(* Logix 5000 project; controller CIP_Sync_Essentials_Sample_Project_2_1 vendor 1 type 14 code 156 rev 34.11; software revision 34.01; part 2 of 4 *)
(* CIP_Axis_Home, continued *)

ROUTINE Logic   (* ladder *)
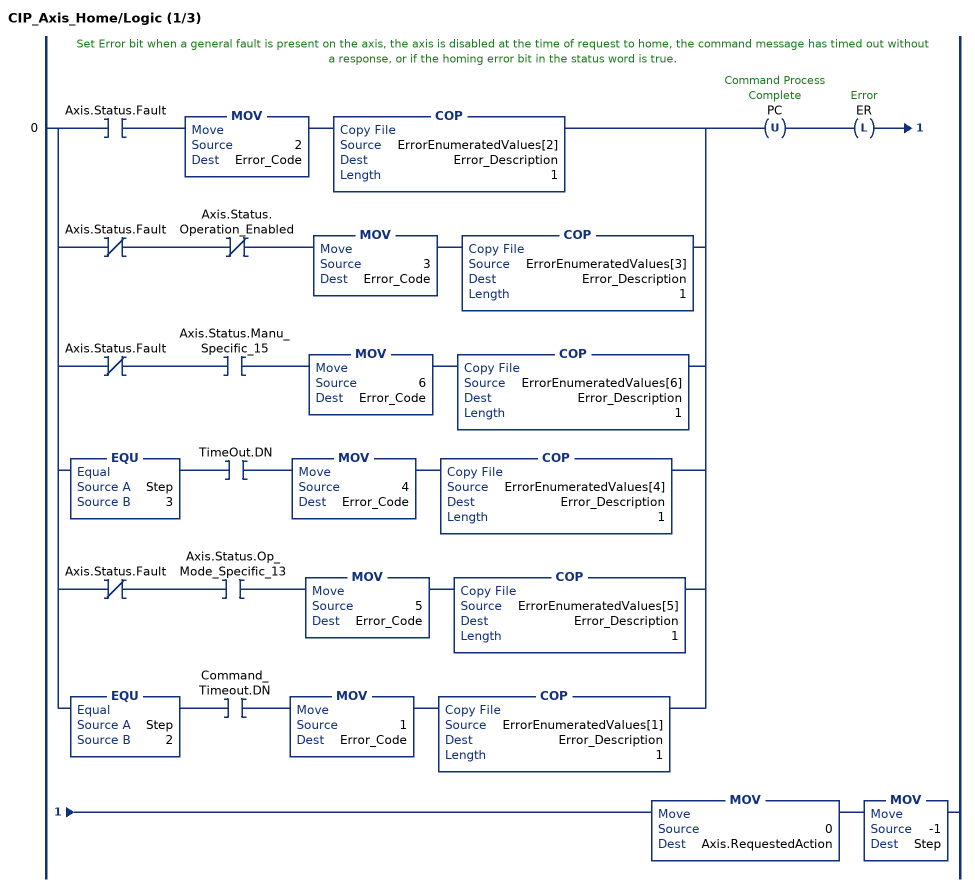
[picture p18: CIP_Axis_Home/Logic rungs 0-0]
   // Set Error bit when a general fault is present on the axis, the axis is disabled at the time of request to home, the command message has timed out without a response, or if the homing error bit in the status word is true.
   0: [XIC(Axis.Status.Fault) MOV(2,Error_Code) COP(ErrorEnumeratedValues[2],Error_Description,1) ,XIO(Axis.Status.Fault) XIO(Axis.Status.Operation_Enabled) MOV(3,Error_Code) COP(ErrorEnumeratedValues[3],Error_Description,1) ,XIO(Axis.Status.Fault) XIC(Axis.Status.Manu_Specific_15) MOV(6,Error_Code) COP(ErrorEnumeratedValues[6],Error_Description,1) ,EQU(Step,3) XIC(TimeOut.DN) MOV(4,Error_Code) COP(ErrorEnumeratedValues[4],Error_Description,1) ,XIO(Axis.Status.Fault) XIC(Axis.Status.Op_Mode_Specific_13) MOV(5,Error_Code) COP(ErrorEnumeratedValues[5],Error_Description,1) ,EQU(Step,2) XIC(Command_Timeout.DN) MOV(1,Error_Code) COP(ErrorEnumeratedValues[1],Error_Description,1) ]OTU(PC)OTL(ER)MOV(0,Axis.RequestedAction)MOV(-1,Step);
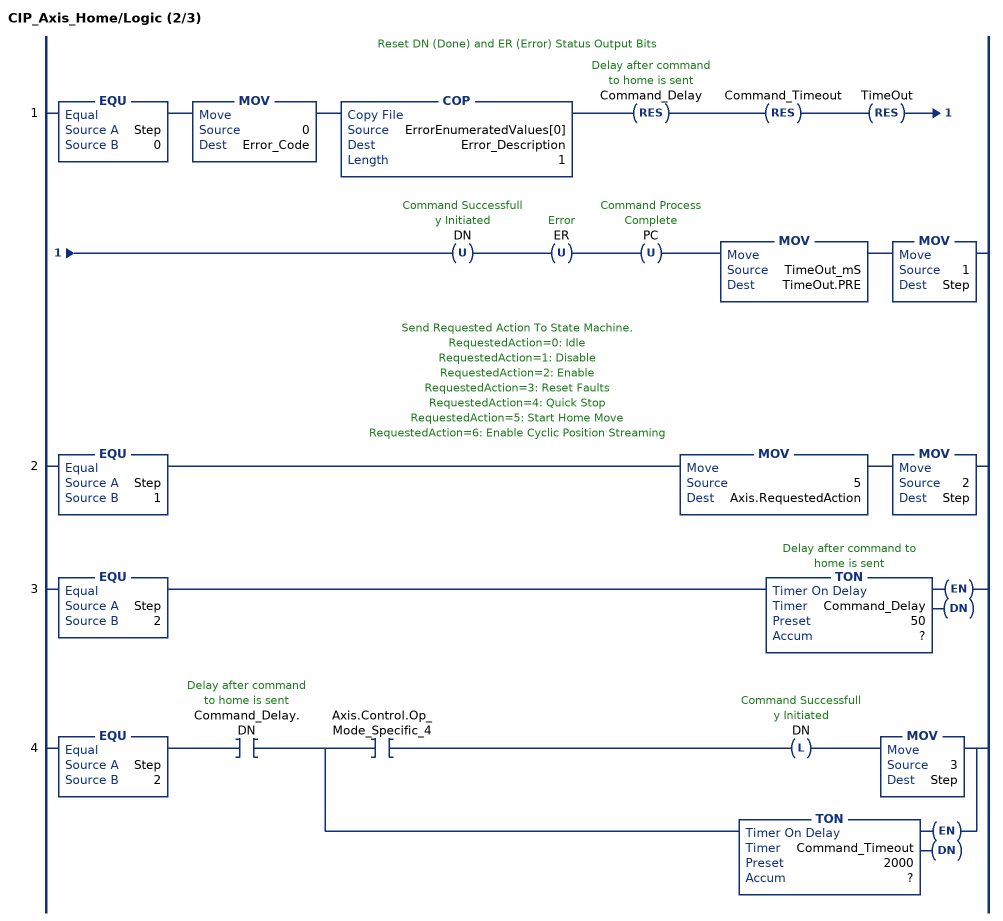
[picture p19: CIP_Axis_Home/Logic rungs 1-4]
   // Reset DN (Done) and ER (Error) Status Output Bits
   1: EQU(Step,0)MOV(0,Error_Code)COP(ErrorEnumeratedValues[0],Error_Description,1)RES(Command_Delay)RES(Command_Timeout)RES(TimeOut)OTU(DN)OTU(ER)OTU(PC)MOV(TimeOut_mS,TimeOut.PRE)MOV(1,Step);
   // Send Requested Action To State Machine.
   // RequestedAction=0: Idle
   // RequestedAction=1: Disable
   // RequestedAction=2: Enable
   // RequestedAction=3: Reset Faults
   // RequestedAction=4: Quick Stop
   // RequestedAction=5: Start Home Move
   // RequestedAction=6: Enable Cyclic Position Streaming
   2: EQU(Step,1)MOV(5,Axis.RequestedAction)MOV(2,Step);
   3: EQU(Step,2)TON(Command_Delay,?,?);
   4: EQU(Step,2)XIC(Command_Delay.DN)[XIC(Axis.Control.Op_Mode_Specific_4) OTL(DN) MOV(3,Step) ,TON(Command_Timeout,?,?) ];
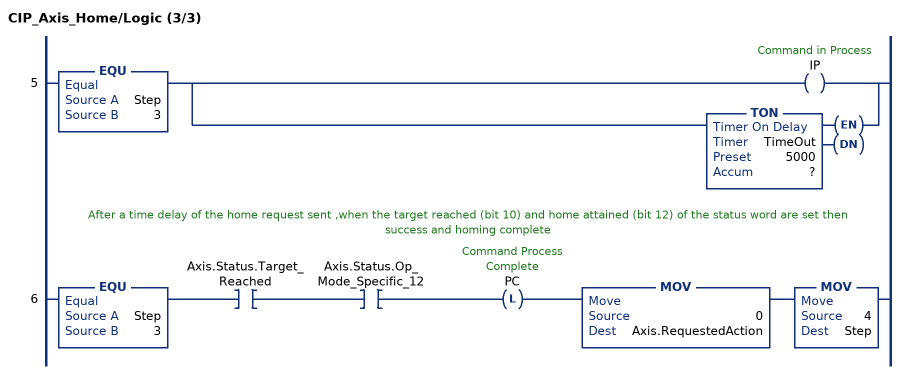
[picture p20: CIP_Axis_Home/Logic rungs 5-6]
   5: EQU(Step,3)[OTE(IP) ,TON(TimeOut,?,?) ];
   // After a time delay of the home request sent ,when the target reached (bit 10) and home attained (bit 12) of the status word are set then success and homing complete
   6: EQU(Step,3)XIC(Axis.Status.Target_Reached)XIC(Axis.Status.Op_Mode_Specific_12)OTL(PC)MOV(0,Axis.RequestedAction)MOV(4,Step);
END_ROUTINE

ROUTINE Prescan   (* ladder *)
// Prescan
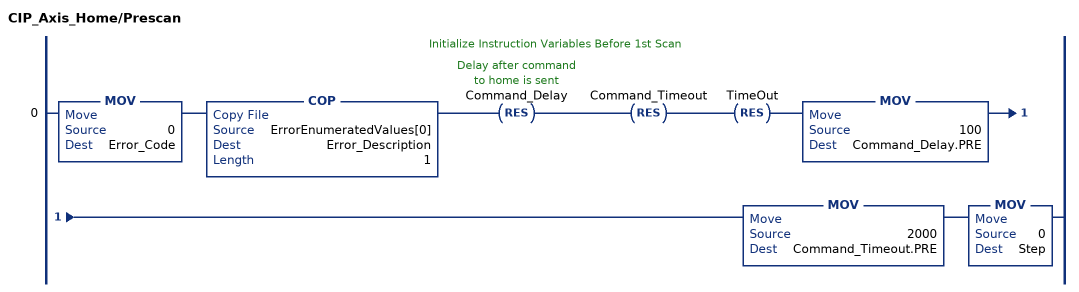
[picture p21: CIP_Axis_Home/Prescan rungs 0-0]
   // Initialize Instruction Variables Before 1st Scan
   0: MOV(0,Error_Code)COP(ErrorEnumeratedValues[0],Error_Description,1)RES(Command_Delay)RES(Command_Timeout)RES(TimeOut)MOV(100,Command_Delay.PRE)MOV(2000,Command_Timeout.PRE)MOV(0,Step);
END_ROUTINE
END_ADD_ON_INSTRUCTION

ADD_ON_INSTRUCTION CIP_Axis_Quick_Stop   (* revision 2.1, ExecutePrescan, ExecuteEnableInFalse *)
// Motion Quick Stop
VAR_OUTPUT
   DN : BOOL; {access Read Only, visible}   // Command Successful
   ER : BOOL; {access Read Only, visible}   // Error
   IP : BOOL; {access Read Only, visible}   // In Progress
   PC : BOOL; {access Read Only, visible}   // Process Complete
END_VAR
VAR_IN_OUT
   Axis : CIP_Axis; {required}
END_VAR
VAR_INPUT
   TimeOut_mS : DINT; {required}
END_VAR
VAR_IN_OUT
   Get_Quick_Stop_Code : MESSAGE; {required}
END_VAR
VAR_INPUT
   Quick_Stop_Option_Code_Read : INT;
   Quick_Stop_Option_Code : INT; {visible}
END_VAR
VAR_OUTPUT
   Error_Code : SINT; {access Read Only, visible}
END_VAR
VAR_IN_OUT
   Error_Description : STRING; {required}
END_VAR
VAR
   One_SHT : BOOL; {access None}
   Step : DINT := 2; {access None}
   Command_Delay : TIMER := (PRE := 100); {access None}
   Command_Timeout : TIMER := (PRE := 2000); {access None}
   ErrorEnumeratedValues : STRING[6] := ([0] := 'No Error', [1] := 'Command Timeout', [2] := 'Axis Faulted', [3] := 'Get Quick Stop MSG Error', [4] := 'Axis Quick Stop Code Not 1,2,5,or 6', [5] := 'Quick Stop Timeout_mS Exceeded'); {access None}
   TimeOut : TIMER := (PRE := 5000); {access None}
END_VAR

ROUTINE EnableInFalse   (* ladder *)
// Enable In False
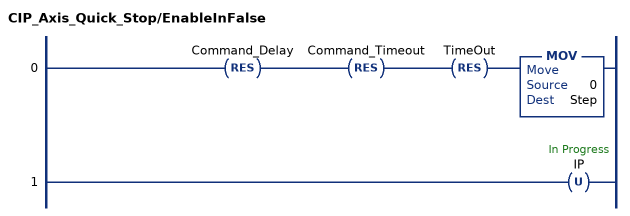
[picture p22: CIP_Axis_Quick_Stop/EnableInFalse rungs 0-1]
   0: RES(Command_Delay)RES(Command_Timeout)RES(TimeOut)MOV(0,Step);
   1: OTU(IP);
END_ROUTINE

ROUTINE Logic   (* ladder *)
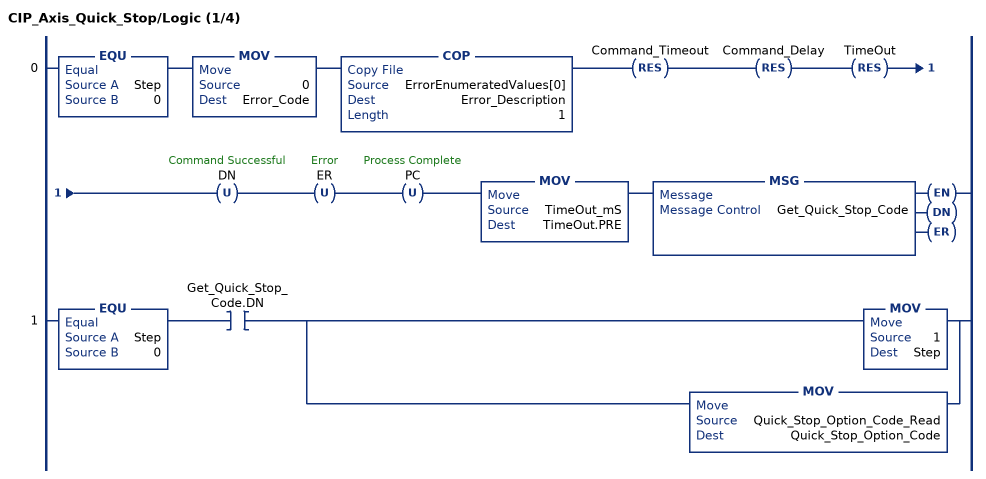
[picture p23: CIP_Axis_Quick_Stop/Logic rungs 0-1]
   0: EQU(Step,0)MOV(0,Error_Code)COP(ErrorEnumeratedValues[0],Error_Description,1)RES(Command_Timeout)RES(Command_Delay)RES(TimeOut)OTU(DN)OTU(ER)OTU(PC)MOV(TimeOut_mS,TimeOut.PRE)MSG(Get_Quick_Stop_Code);
   1: EQU(Step,0)XIC(Get_Quick_Stop_Code.DN)[MOV(1,Step) ,MOV(Quick_Stop_Option_Code_Read,Quick_Stop_Option_Code) ];
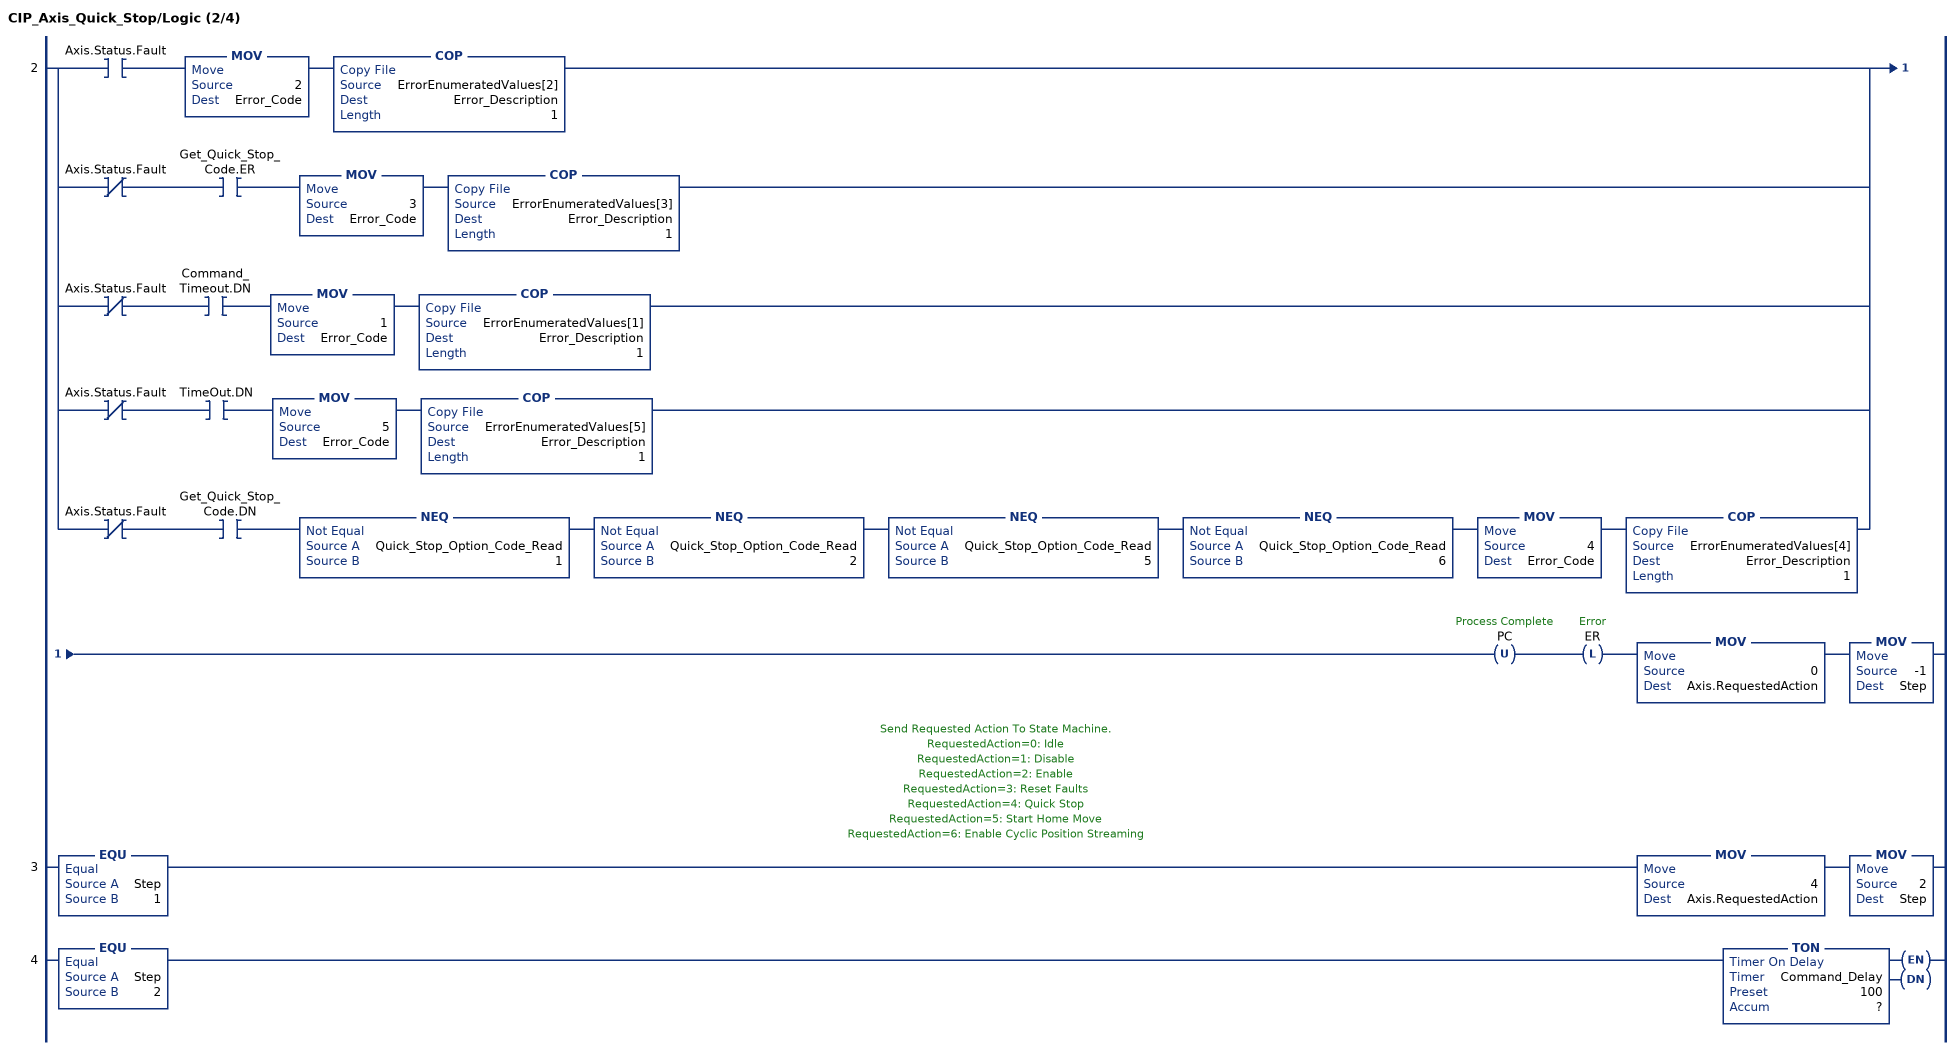
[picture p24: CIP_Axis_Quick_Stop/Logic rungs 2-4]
   2: [XIC(Axis.Status.Fault) MOV(2,Error_Code) COP(ErrorEnumeratedValues[2],Error_Description,1) ,XIO(Axis.Status.Fault) XIC(Get_Quick_Stop_Code.ER) MOV(3,Error_Code) COP(ErrorEnumeratedValues[3],Error_Description,1) ,XIO(Axis.Status.Fault) XIC(Command_Timeout.DN) MOV(1,Error_Code) COP(ErrorEnumeratedValues[1],Error_Description,1) ,XIO(Axis.Status.Fault) XIC(TimeOut.DN) MOV(5,Error_Code) COP(ErrorEnumeratedValues[5],Error_Description,1) ,XIO(Axis.Status.Fault) XIC(Get_Quick_Stop_Code.DN) NEQ(Quick_Stop_Option_Code_Read,1) NEQ(Quick_Stop_Option_Code_Read,2) NEQ(Quick_Stop_Option_Code_Read,5) NEQ(Quick_Stop_Option_Code_Read,6) MOV(4,Error_Code) COP(ErrorEnumeratedValues[4],Error_Description,1) ]OTU(PC)OTL(ER)MOV(0,Axis.RequestedAction)MOV(-1,Step);
   // Send Requested Action To State Machine.
   // RequestedAction=0: Idle
   // RequestedAction=1: Disable
   // RequestedAction=2: Enable
   // RequestedAction=3: Reset Faults
   // RequestedAction=4: Quick Stop
   // RequestedAction=5: Start Home Move
   // RequestedAction=6: Enable Cyclic Position Streaming
   3: EQU(Step,1)MOV(4,Axis.RequestedAction)MOV(2,Step);
   4: EQU(Step,2)TON(Command_Delay,?,?);
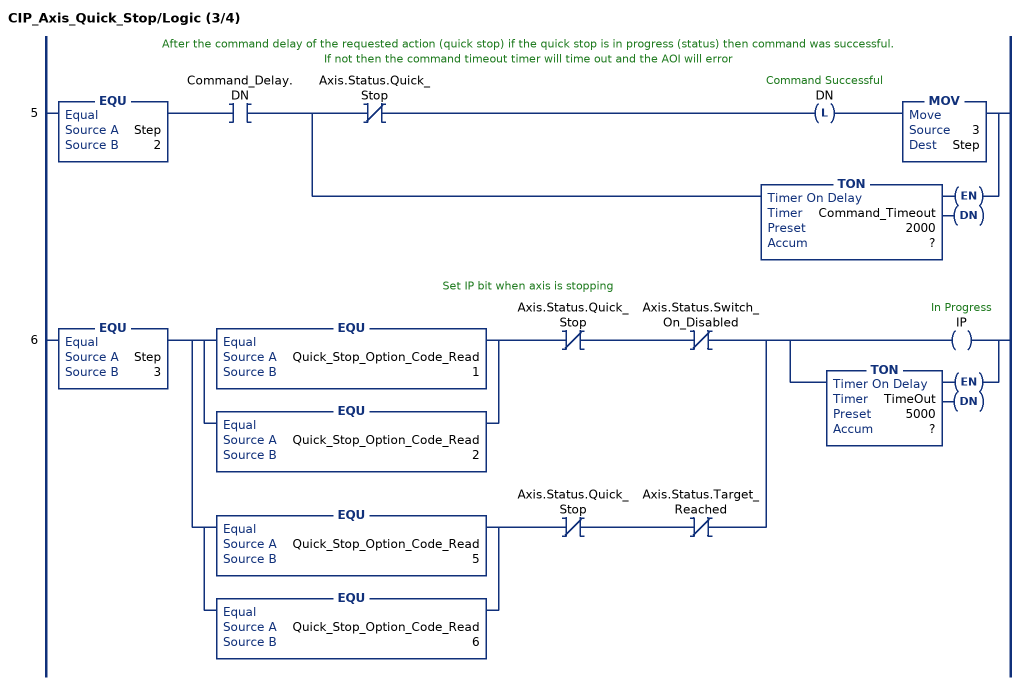
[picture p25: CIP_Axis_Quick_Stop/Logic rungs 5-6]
   // After the command delay of the requested action (quick stop) if the quick stop is in progress (status) then command was successful.
   //  If not then the command timeout timer will time out and the AOI will error
   5: EQU(Step,2)XIC(Command_Delay.DN)[XIO(Axis.Status.Quick_Stop) OTL(DN) MOV(3,Step) ,TON(Command_Timeout,?,?) ];
   // Set IP bit when axis is stopping
   6: EQU(Step,3)[[EQU(Quick_Stop_Option_Code_Read,1) ,EQU(Quick_Stop_Option_Code_Read,2) ] XIO(Axis.Status.Quick_Stop) XIO(Axis.Status.Switch_On_Disabled) ,[EQU(Quick_Stop_Option_Code_Read,5) ,EQU(Quick_Stop_Option_Code_Read,6) ] XIO(Axis.Status.Quick_Stop) XIO(Axis.Status.Target_Reached) ][OTE(IP) ,TON(TimeOut,?,?) ];
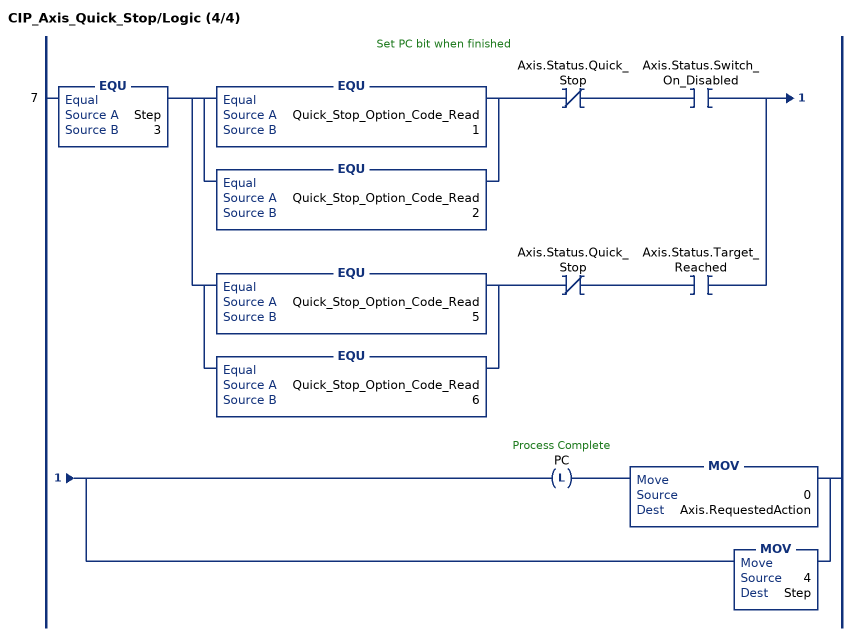
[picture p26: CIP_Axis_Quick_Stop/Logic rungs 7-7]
   // Set PC bit when finished
   7: EQU(Step,3)[[EQU(Quick_Stop_Option_Code_Read,1) ,EQU(Quick_Stop_Option_Code_Read,2) ] XIO(Axis.Status.Quick_Stop) XIC(Axis.Status.Switch_On_Disabled) ,[EQU(Quick_Stop_Option_Code_Read,5) ,EQU(Quick_Stop_Option_Code_Read,6) ] XIO(Axis.Status.Quick_Stop) XIC(Axis.Status.Target_Reached) ][OTL(PC) MOV(0,Axis.RequestedAction) ,MOV(4,Step) ];
END_ROUTINE

ROUTINE Prescan   (* ladder *)
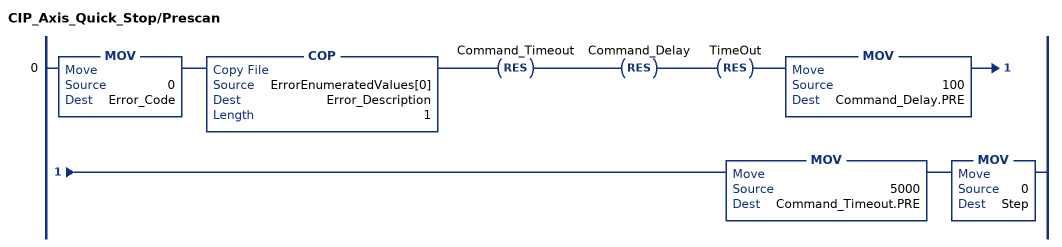
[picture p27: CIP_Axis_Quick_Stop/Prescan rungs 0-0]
   0: MOV(0,Error_Code)COP(ErrorEnumeratedValues[0],Error_Description,1)RES(Command_Timeout)RES(Command_Delay)RES(TimeOut)MOV(100,Command_Delay.PRE)MOV(5000,Command_Timeout.PRE)MOV(0,Step);
END_ROUTINE
END_ADD_ON_INSTRUCTION

ADD_ON_INSTRUCTION CIP_Axis_State_Machine   (* revision 2.1, ExecutePrescan *)
// CIP Sync Axis State Machine
// Revision note:
// Updated to indicate an error in either Update Period MSG or Unwind MSG.
// Changed Quick Stop Active status output to Quick Stop to report the bit status and not the state.
VAR_IN_OUT
   Axis : CIP_Axis; {required}
   VirtualAxis : AXIS_VIRTUAL; {required}
   MotionGroup : MOTION_GROUP; {required}
   UpdatePeriodMsg : MESSAGE; {required}
   UnwindMsg : MESSAGE; {required}
END_VAR
VAR_OUTPUT
   RequestedAction : INT; {access Read Only, visible}
   StateMachineErrorCode : INT; {access Read Only, visible}
END_VAR
VAR_IN_OUT
   StateMachineErrorDescription : STRING; {required}
END_VAR
VAR_OUTPUT
   StateMachineCurrentState : INT; {access Read Only, visible}
END_VAR
VAR_IN_OUT
   StateMachineCurrentStateDescription : STRING; {required}
END_VAR
VAR_OUTPUT
   UpdatePeriod : DINT; {access None}
   Unwind : DINT; {access None}
   AxisControlWord : INT; {access Read Only, visible}
   IP : BOOL; {access Read Only, visible}
   DN : BOOL; {access Read Only, visible}
   ER : BOOL; {access Read Only, visible}
   AxisReadyToSwitchOn : BOOL; {access Read Only, visible}
   AxisSwitchedOn : BOOL; {access Read Only, visible}
   AxisOperationEnabled : BOOL; {access Read Only, visible}
   AxisFaulted : BOOL; {access Read Only, visible}
   AxisVoltageEnabled : BOOL; {access Read Only, visible}
   AxisQuickStop : BOOL; {access Read Only, visible}
   AxisSwitchOnDisabled : BOOL; {access Read Only, visible}
   AxisWarning : BOOL; {access Read Only, visible}
   AxisSTO : BOOL; {access Read Only, visible}
   AxisRemote : BOOL; {access Read Only, visible}
   AxisTargetReached : BOOL; {access Read Only, visible}
   AxisInternalLimitActive : BOOL; {access Read Only, visible}
   AxisHomeAttained : BOOL; {access Read Only, visible}
   AxisHomingError : BOOL; {access Read Only, visible}
   AxisMotionModeHoming : BOOL; {access Read Only, visible}
   AxisMotionModeCyclicPosition : BOOL; {access Read Only, visible}
   AxisFollowingError : BOOL; {access Read Only, visible}
   AxisStreamingActive : BOOL; {access Read Only, visible}
END_VAR
VAR
   NextState : DINT; {access None}
   CycleStartTime : DINT[2]; {access None}
   InProgressOneShot : BOOL; {access None}
   AxisMRP : MOTION_INSTRUCTION; {access None}
   AxisPosition : DINT; {access None}
   PrevRequestedAction : DINT; {access None}
   Action : DINT; {access None}
   StateEnumeratedValues : STRING[8] := ([0] := 'Not Ready To Switch On', [1] := 'Switch On Disabled', [2] := 'Ready To Switch On', [3] := 'Switched On', [4] := 'Operation Enabled', [5] := 'Quick Stop Active', [6] := 'Fault Reaction Active', [7] := 'Faulted'); {access None}
        [0].DATA   // STATE0
        [1].DATA   // STATE1
        [2].DATA   // STATE2
   ErrorEnumeratedValues : STRING[13] := ([0] := 'In Fault Reaction Active State while trying to disable', [1] := 'In Fault State while trying to disable', [2] := 'In Fault Reaction Active State while trying to enable', [3] := 'In Fault State while trying to enable', [4] := 'Not In Operation Enable or Quick Stop state after requesting Quick Stop State', [5] := 'Homing Error State bit is set', [6] := 'Not In Operation Enable State', [7] := 'Home Attained status bit is cleared', [8] := 'Cyclic Position Following Error bit is set', [9] := 'Error in MRP instruction used to synch drive axis with virtual axis ,not streaming', [10] := 'No Error', [11] := 'Update Period MSG error', [12] := 'Unwind MSG error'); {access None}
   UpdatePeriodMsgSent : BOOL; {access None}
   UnwindMsgSent : BOOL; {access None}
   IsRotary : SINT; {access None}
END_VAR

ROUTINE Logic   (* ladder *)
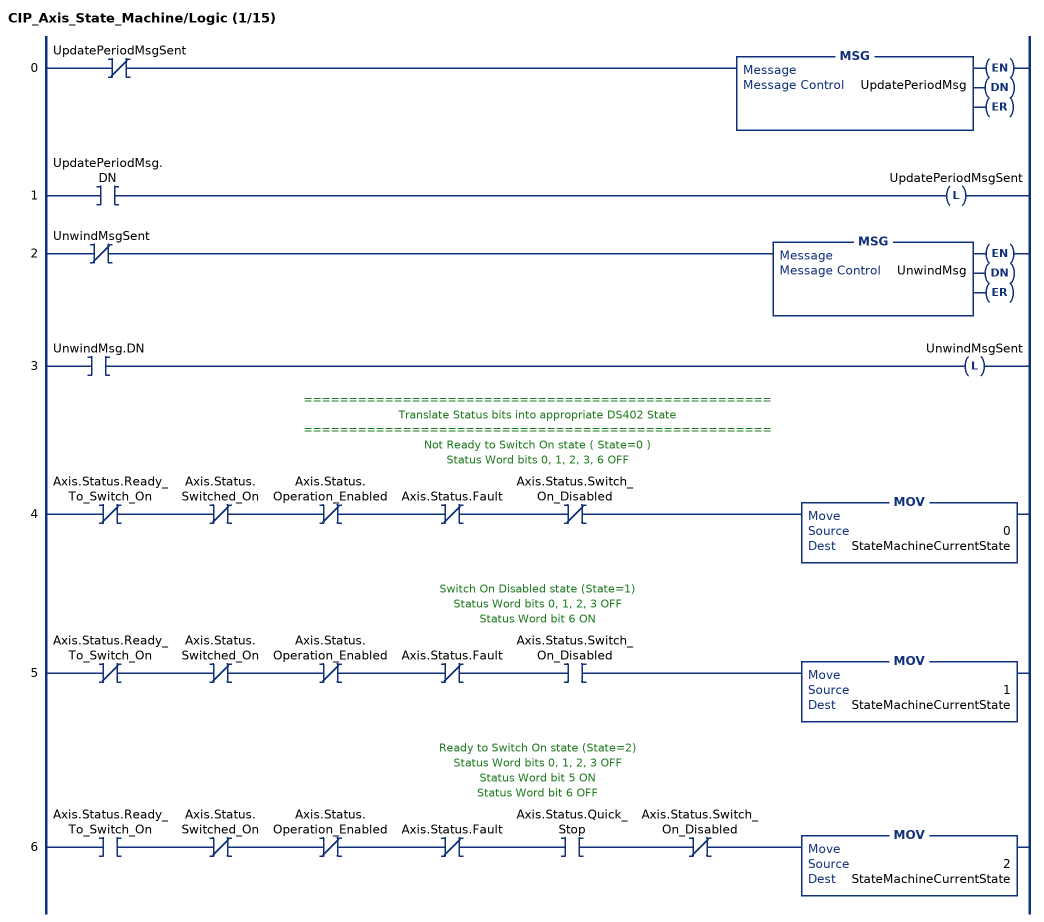
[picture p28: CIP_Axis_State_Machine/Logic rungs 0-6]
   0: XIO(UpdatePeriodMsgSent)MSG(UpdatePeriodMsg);
   1: XIC(UpdatePeriodMsg.DN)OTL(UpdatePeriodMsgSent);
   2: XIO(UnwindMsgSent)MSG(UnwindMsg);
   3: XIC(UnwindMsg.DN)OTL(UnwindMsgSent);
   // ====================================================
   // Translate Status bits into appropriate DS402 State
   // ====================================================
   // Not Ready to Switch On state ( State=0 )
   // Status Word bits 0, 1, 2, 3, 6 OFF
   4: XIO(Axis.Status.Ready_To_Switch_On)XIO(Axis.Status.Switched_On)XIO(Axis.Status.Operation_Enabled)XIO(Axis.Status.Fault)XIO(Axis.Status.Switch_On_Disabled)MOV(0,StateMachineCurrentState);
   // Switch On Disabled state (State=1)
   // Status Word bits 0, 1, 2, 3 OFF
   // Status Word bit 6 ON
   5: XIO(Axis.Status.Ready_To_Switch_On)XIO(Axis.Status.Switched_On)XIO(Axis.Status.Operation_Enabled)XIO(Axis.Status.Fault)XIC(Axis.Status.Switch_On_Disabled)MOV(1,StateMachineCurrentState);
   // Ready to Switch On state (State=2)
   // Status Word bits 0, 1, 2, 3 OFF
   // Status Word bit 5 ON
   // Status Word bit 6 OFF
   6: XIC(Axis.Status.Ready_To_Switch_On)XIO(Axis.Status.Switched_On)XIO(Axis.Status.Operation_Enabled)XIO(Axis.Status.Fault)XIC(Axis.Status.Quick_Stop)XIO(Axis.Status.Switch_On_Disabled)MOV(2,StateMachineCurrentState);
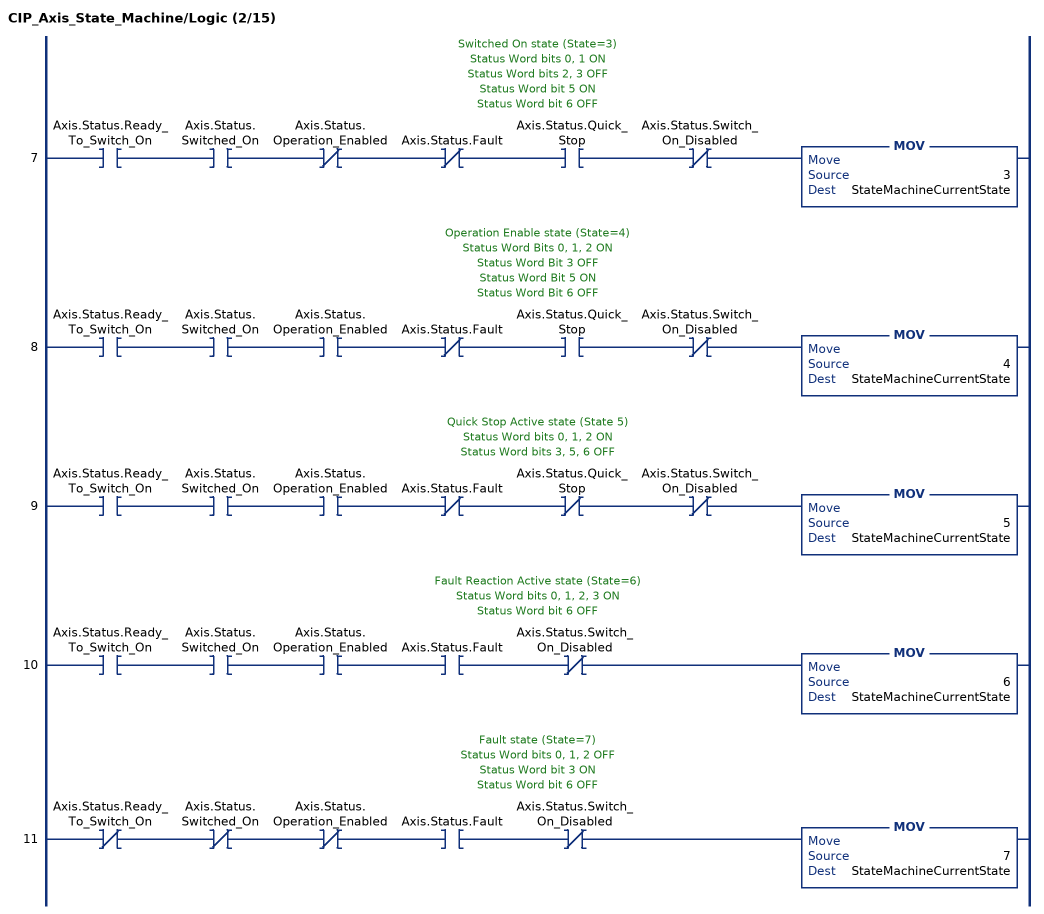
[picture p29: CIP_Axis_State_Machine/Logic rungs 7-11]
   // Switched On state (State=3)
   // Status Word bits 0, 1 ON
   // Status Word bits 2, 3 OFF
   // Status Word bit 5 ON
   // Status Word bit 6 OFF
   7: XIC(Axis.Status.Ready_To_Switch_On)XIC(Axis.Status.Switched_On)XIO(Axis.Status.Operation_Enabled)XIO(Axis.Status.Fault)XIC(Axis.Status.Quick_Stop)XIO(Axis.Status.Switch_On_Disabled)MOV(3,StateMachineCurrentState);
   // Operation Enable state (State=4)
   // Status Word Bits 0, 1, 2 ON
   // Status Word Bit 3 OFF
   // Status Word Bit 5 ON
   // Status Word Bit 6 OFF
   8: XIC(Axis.Status.Ready_To_Switch_On)XIC(Axis.Status.Switched_On)XIC(Axis.Status.Operation_Enabled)XIO(Axis.Status.Fault)XIC(Axis.Status.Quick_Stop)XIO(Axis.Status.Switch_On_Disabled)MOV(4,StateMachineCurrentState);
   // Quick Stop Active state (State 5)
   // Status Word bits 0, 1, 2 ON
   // Status Word bits 3, 5, 6 OFF
   9: XIC(Axis.Status.Ready_To_Switch_On)XIC(Axis.Status.Switched_On)XIC(Axis.Status.Operation_Enabled)XIO(Axis.Status.Fault)XIO(Axis.Status.Quick_Stop)XIO(Axis.Status.Switch_On_Disabled)MOV(5,StateMachineCurrentState);
   // Fault Reaction Active state (State=6)
   // Status Word bits 0, 1, 2, 3 ON
   // Status Word bit 6 OFF
   10: XIC(Axis.Status.Ready_To_Switch_On)XIC(Axis.Status.Switched_On)XIC(Axis.Status.Operation_Enabled)XIC(Axis.Status.Fault)XIO(Axis.Status.Switch_On_Disabled)MOV(6,StateMachineCurrentState);
   // Fault state (State=7)
   // Status Word bits 0, 1, 2 OFF
   // Status Word bit 3 ON
   // Status Word bit 6 OFF
   11: XIO(Axis.Status.Ready_To_Switch_On)XIO(Axis.Status.Switched_On)XIO(Axis.Status.Operation_Enabled)XIC(Axis.Status.Fault)XIO(Axis.Status.Switch_On_Disabled)MOV(7,StateMachineCurrentState);
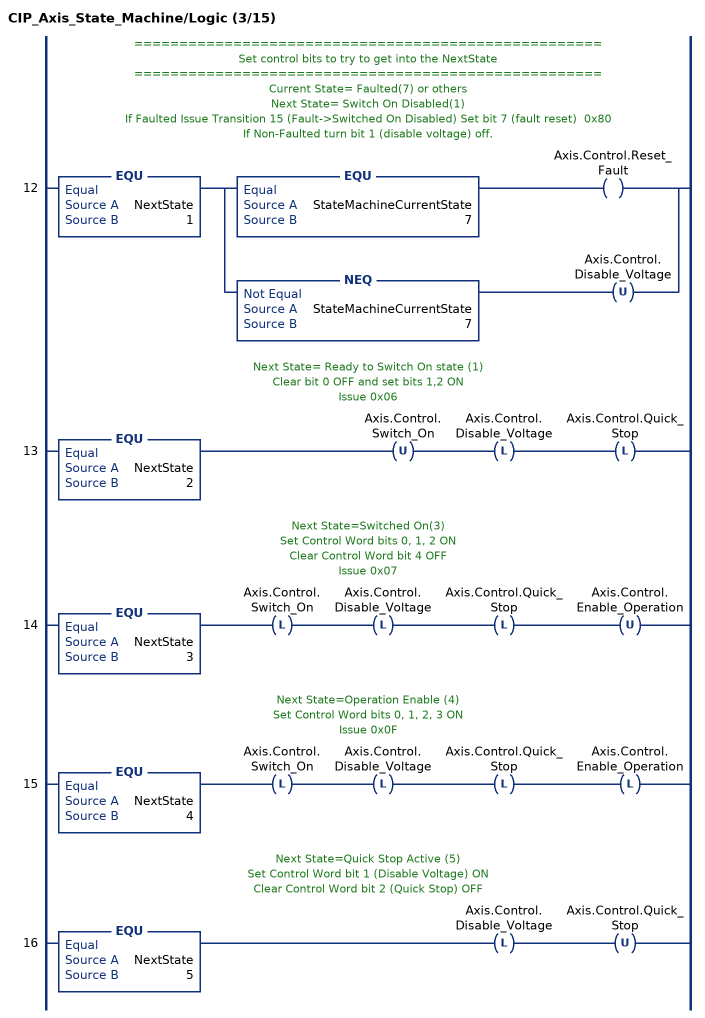
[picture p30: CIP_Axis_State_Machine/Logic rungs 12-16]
   // ====================================================
   // Set control bits to try to get into the NextState
   // ====================================================
   // Current State= Faulted(7) or others
   // Next State= Switch On Disabled(1)
   // If Faulted Issue Transition 15 (Fault->Switched On Disabled) Set bit 7 (fault reset)  0x80
   // If Non-Faulted turn bit 1 (disable voltage) off.
   12: EQU(NextState,1)[EQU(StateMachineCurrentState,7) OTE(Axis.Control.Reset_Fault) ,NEQ(StateMachineCurrentState,7) OTU(Axis.Control.Disable_Voltage) ];
   // Next State= Ready to Switch On state (1)
   // Clear bit 0 OFF and set bits 1,2 ON
   // Issue 0x06
   13: EQU(NextState,2)OTU(Axis.Control.Switch_On)OTL(Axis.Control.Disable_Voltage)OTL(Axis.Control.Quick_Stop);
   // Next State=Switched On(3)
   // Set Control Word bits 0, 1, 2 ON
   // Clear Control Word bit 4 OFF
   // Issue 0x07
   14: EQU(NextState,3)OTL(Axis.Control.Switch_On)OTL(Axis.Control.Disable_Voltage)OTL(Axis.Control.Quick_Stop)OTU(Axis.Control.Enable_Operation);
   // Next State=Operation Enable (4)
   // Set Control Word bits 0, 1, 2, 3 ON
   // Issue 0x0F
   15: EQU(NextState,4)OTL(Axis.Control.Switch_On)OTL(Axis.Control.Disable_Voltage)OTL(Axis.Control.Quick_Stop)OTL(Axis.Control.Enable_Operation);
   // Next State=Quick Stop Active (5)
   // Set Control Word bit 1 (Disable Voltage) ON
   // Clear Control Word bit 2 (Quick Stop) OFF
   16: EQU(NextState,5)OTL(Axis.Control.Disable_Voltage)OTU(Axis.Control.Quick_Stop);
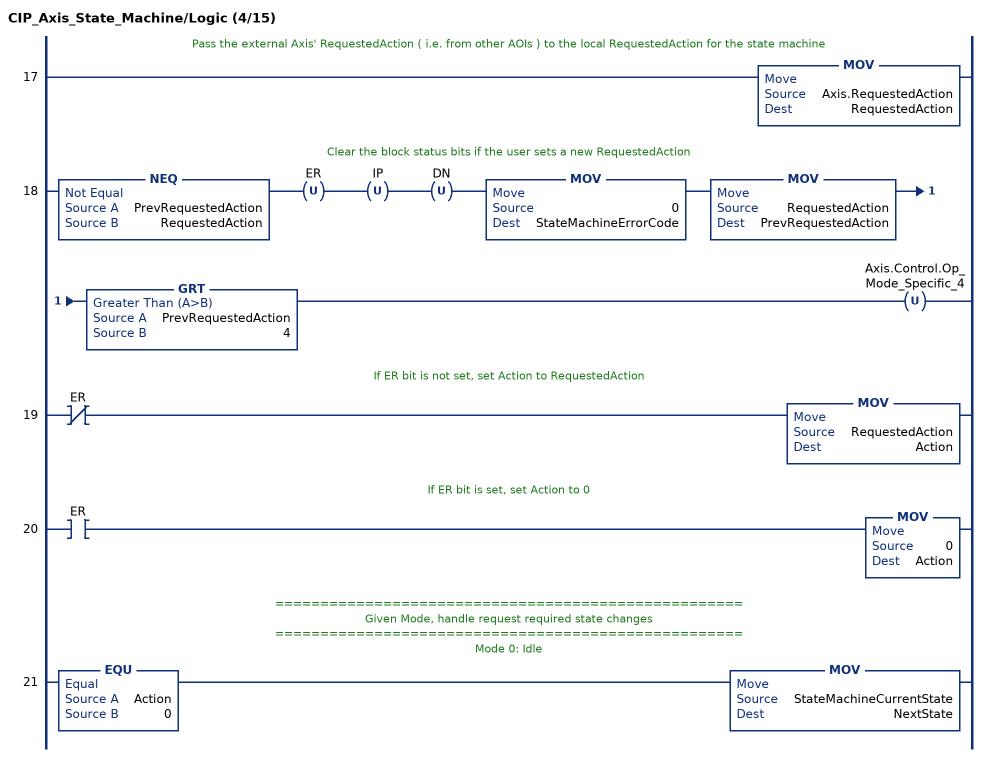
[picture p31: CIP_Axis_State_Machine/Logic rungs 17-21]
   // Pass the external Axis' RequestedAction ( i.e. from other AOIs ) to the local RequestedAction for the state machine
   17: MOV(Axis.RequestedAction,RequestedAction);
   // Clear the block status bits if the user sets a new RequestedAction
   18: NEQ(PrevRequestedAction,RequestedAction)OTU(ER)OTU(IP)OTU(DN)MOV(0,StateMachineErrorCode)MOV(RequestedAction,PrevRequestedAction)GRT(PrevRequestedAction,4)OTU(Axis.Control.Op_Mode_Specific_4);
   // If ER bit is not set, set Action to RequestedAction
   19: XIO(ER)MOV(RequestedAction,Action);
   // If ER bit is set, set Action to 0
   20: XIC(ER)MOV(0,Action);
   // ====================================================
   // Given Mode, handle request required state changes
   // ====================================================
   // Mode 0: Idle
   21: EQU(Action,0)MOV(StateMachineCurrentState,NextState);
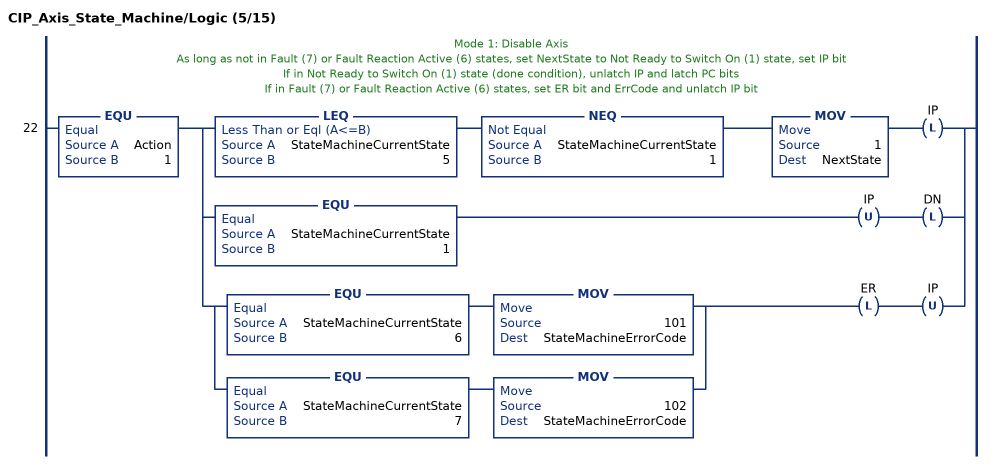
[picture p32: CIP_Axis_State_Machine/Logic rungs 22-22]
   // Mode 1: Disable Axis
   // As long as not in Fault (7) or Fault Reaction Active (6) states, set NextState to Not Ready to Switch On (1) state, set IP bit
   // If in Not Ready to Switch On (1) state (done condition), unlatch IP and latch PC bits
   // If in Fault (7) or Fault Reaction Active (6) states, set ER bit and ErrCode and unlatch IP bit
   22: EQU(Action,1)[LEQ(StateMachineCurrentState,5) NEQ(StateMachineCurrentState,1) MOV(1,NextState) OTL(IP) ,EQU(StateMachineCurrentState,1) OTU(IP) OTL(DN) ,[EQU(StateMachineCurrentState,6) MOV(101,StateMachineErrorCode) ,EQU(StateMachineCurrentState,7) MOV(102,StateMachineErrorCode) ] OTL(ER) OTU(IP) ];
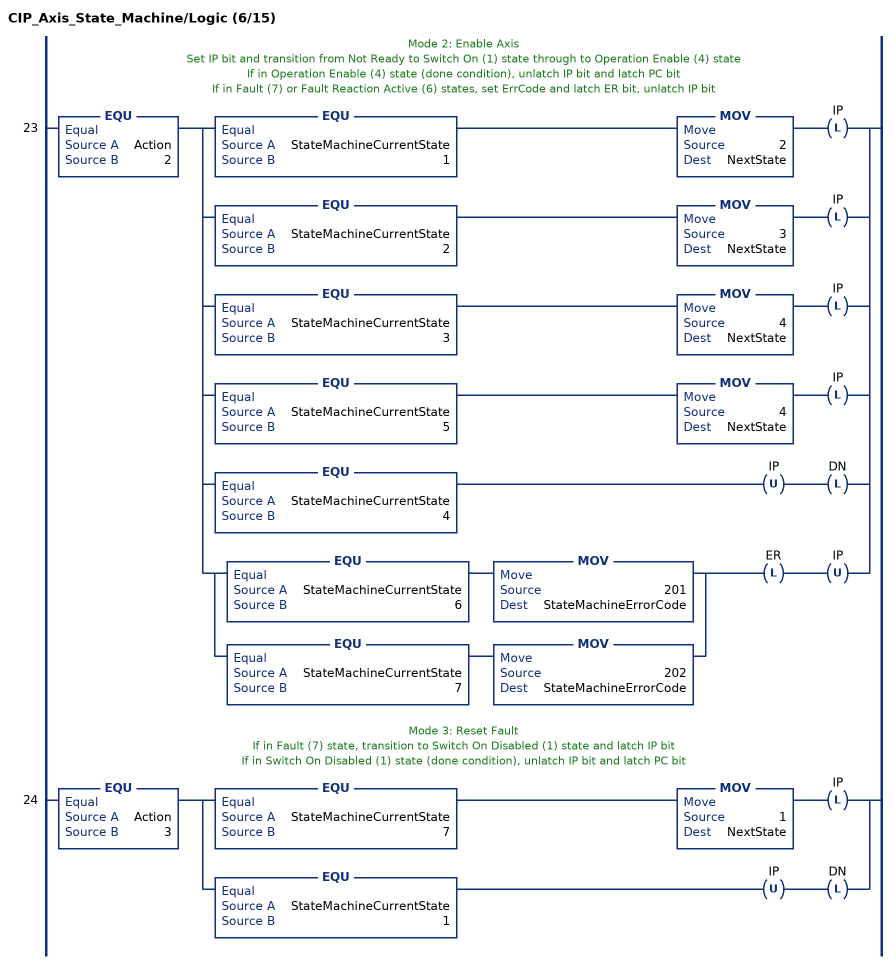
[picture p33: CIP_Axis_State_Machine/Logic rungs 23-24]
   // Mode 2: Enable Axis
   // Set IP bit and transition from Not Ready to Switch On (1) state through to Operation Enable (4) state
   // If in Operation Enable (4) state (done condition), unlatch IP bit and latch PC bit
   // If in Fault (7) or Fault Reaction Active (6) states, set ErrCode and latch ER bit, unlatch IP bit
   23: EQU(Action,2)[EQU(StateMachineCurrentState,1) MOV(2,NextState) OTL(IP) ,EQU(StateMachineCurrentState,2) MOV(3,NextState) OTL(IP) ,EQU(StateMachineCurrentState,3) MOV(4,NextState) OTL(IP) ,EQU(StateMachineCurrentState,5) MOV(4,NextState) OTL(IP) ,EQU(StateMachineCurrentState,4) OTU(IP) OTL(DN) ,[EQU(StateMachineCurrentState,6) MOV(201,StateMachineErrorCode) ,EQU(StateMachineCurrentState,7) MOV(202,StateMachineErrorCode) ] OTL(ER) OTU(IP) ];
   // Mode 3: Reset Fault
   // If in Fault (7) state, transition to Switch On Disabled (1) state and latch IP bit
   // If in Switch On Disabled (1) state (done condition), unlatch IP bit and latch PC bit
   24: EQU(Action,3)[EQU(StateMachineCurrentState,7) MOV(1,NextState) OTL(IP) ,EQU(StateMachineCurrentState,1) OTU(IP) OTL(DN) ];
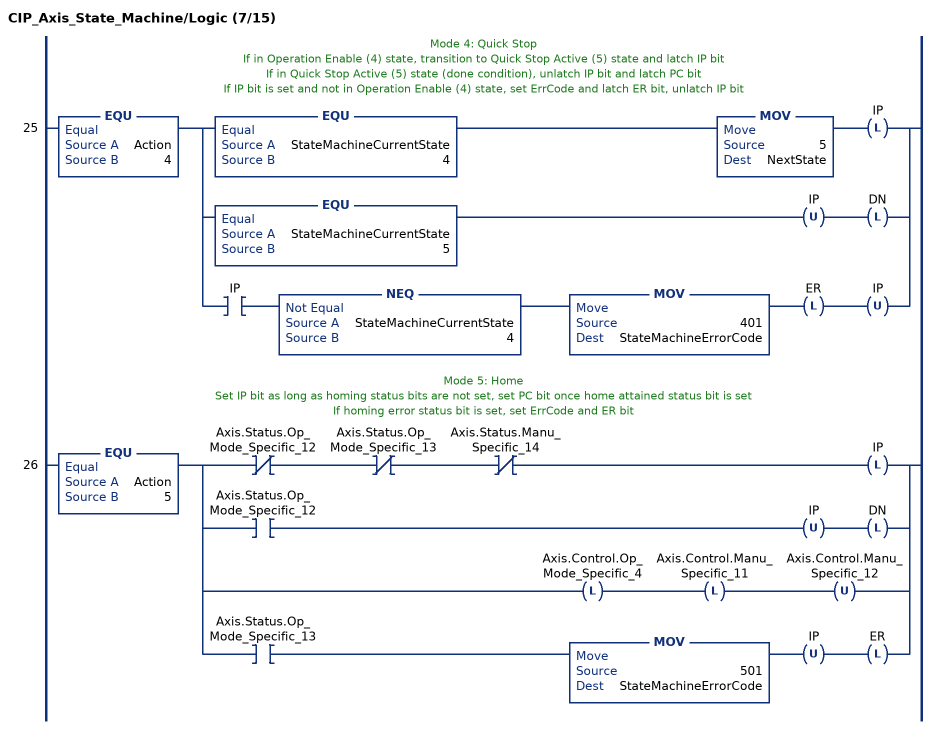
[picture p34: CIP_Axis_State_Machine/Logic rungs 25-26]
   // Mode 4: Quick Stop
   // If in Operation Enable (4) state, transition to Quick Stop Active (5) state and latch IP bit
   // If in Quick Stop Active (5) state (done condition), unlatch IP bit and latch PC bit
   // If IP bit is set and not in Operation Enable (4) state, set ErrCode and latch ER bit, unlatch IP bit
   25: EQU(Action,4)[EQU(StateMachineCurrentState,4) MOV(5,NextState) OTL(IP) ,EQU(StateMachineCurrentState,5) OTU(IP) OTL(DN) ,XIC(IP) NEQ(StateMachineCurrentState,4) MOV(401,StateMachineErrorCode) OTL(ER) OTU(IP) ];
   // Mode 5: Home
   // Set IP bit as long as homing status bits are not set, set PC bit once home attained status bit is set
   // If homing error status bit is set, set ErrCode and ER bit
   26: EQU(Action,5)[XIO(Axis.Status.Op_Mode_Specific_12) XIO(Axis.Status.Op_Mode_Specific_13) XIO(Axis.Status.Manu_Specific_14) OTL(IP) ,XIC(Axis.Status.Op_Mode_Specific_12) OTU(IP) OTL(DN) ,OTL(Axis.Control.Op_Mode_Specific_4) OTL(Axis.Control.Manu_Specific_11) OTU(Axis.Control.Manu_Specific_12) ,XIC(Axis.Status.Op_Mode_Specific_13) MOV(501,StateMachineErrorCode) OTU(IP) OTL(ER) ];
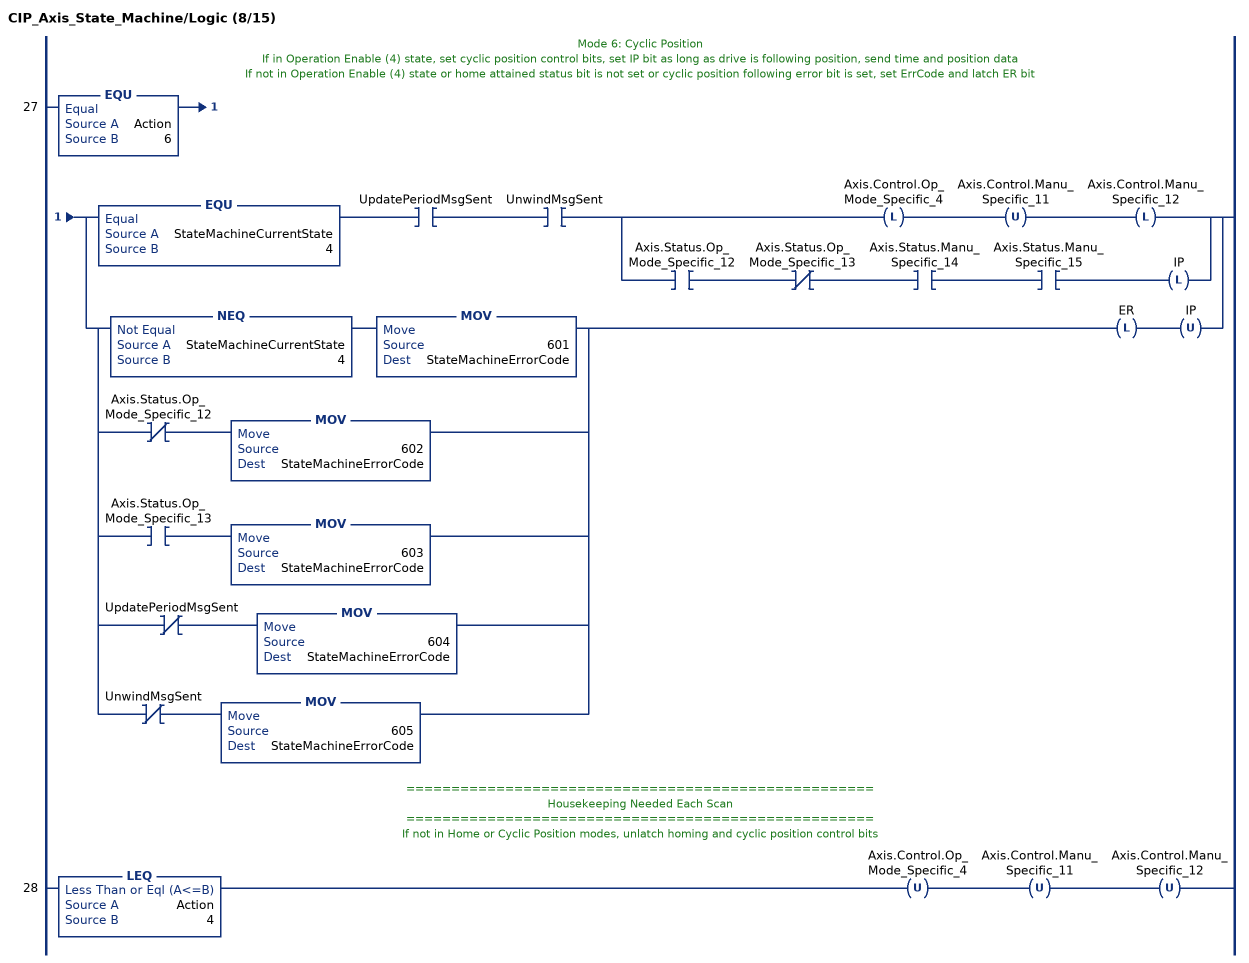
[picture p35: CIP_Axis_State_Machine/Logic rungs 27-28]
   // Mode 6: Cyclic Position
   // If in Operation Enable (4) state, set cyclic position control bits, set IP bit as long as drive is following position, send time and position data
   // If not in Operation Enable (4) state or home attained status bit is not set or cyclic position following error bit is set, set ErrCode and latch ER bit
   27: EQU(Action,6)[EQU(StateMachineCurrentState,4) XIC(UpdatePeriodMsgSent) XIC(UnwindMsgSent) [OTL(Axis.Control.Op_Mode_Specific_4) OTU(Axis.Control.Manu_Specific_11) OTL(Axis.Control.Manu_Specific_12) ,XIC(Axis.Status.Op_Mode_Specific_12) XIO(Axis.Status.Op_Mode_Specific_13) XIC(Axis.Status.Manu_Specific_14) XIC(Axis.Status.Manu_Specific_15) OTL(IP) ] ,[NEQ(StateMachineCurrentState,4) MOV(601,StateMachineErrorCode) ,XIO(Axis.Status.Op_Mode_Specific_12) MOV(602,StateMachineErrorCode) ,XIC(Axis.Status.Op_Mode_Specific_13) MOV(603,StateMachineErrorCode) ,XIO(UpdatePeriodMsgSent) MOV(604,StateMachineErrorCode) ,XIO(UnwindMsgSent) MOV(605,StateMachineErrorCode) ] OTL(ER) OTU(IP) ];
   // ====================================================
   // Housekeeping Needed Each Scan
   // ====================================================
   // If not in Home or Cyclic Position modes, unlatch homing and cyclic position control bits
   28: LEQ(Action,4)OTU(Axis.Control.Op_Mode_Specific_4)OTU(Axis.Control.Manu_Specific_11)OTU(Axis.Control.Manu_Specific_12);
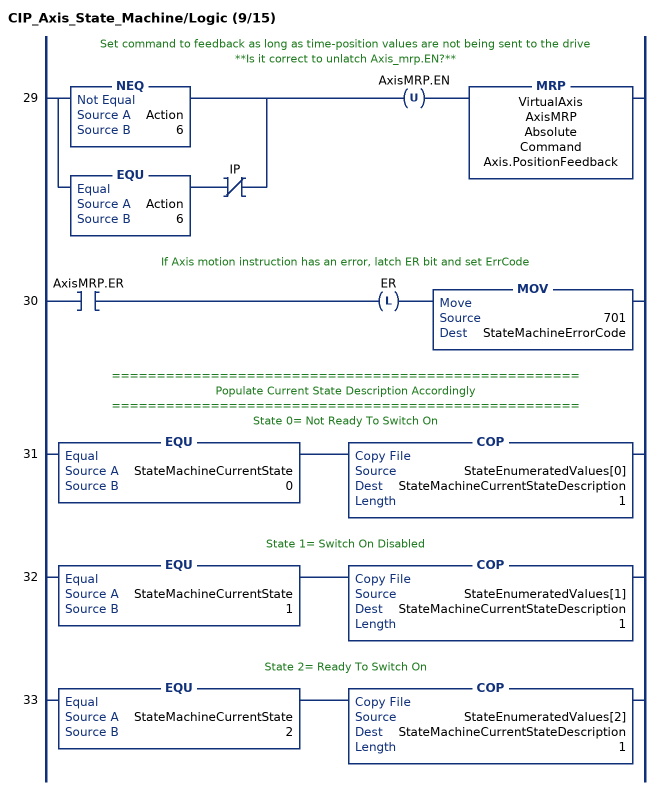
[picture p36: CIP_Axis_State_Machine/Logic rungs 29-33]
   // Set command to feedback as long as time-position values are not being sent to the drive
   // **Is it correct to unlatch Axis_mrp.EN?**
   29: [NEQ(Action,6) ,EQU(Action,6) XIO(IP) ]OTU(AxisMRP.EN)MRP(VirtualAxis,AxisMRP,Absolute,Command,Axis.PositionFeedback);
   // If Axis motion instruction has an error, latch ER bit and set ErrCode
   30: XIC(AxisMRP.ER)OTL(ER)MOV(701,StateMachineErrorCode);
   // ====================================================
   // Populate Current State Description Accordingly
   // ====================================================
   // State 0= Not Ready To Switch On
   31: EQU(StateMachineCurrentState,0)COP(StateEnumeratedValues[0],StateMachineCurrentStateDescription,1);
   // State 1= Switch On Disabled
   32: EQU(StateMachineCurrentState,1)COP(StateEnumeratedValues[1],StateMachineCurrentStateDescription,1);
   // State 2= Ready To Switch On
   33: EQU(StateMachineCurrentState,2)COP(StateEnumeratedValues[2],StateMachineCurrentStateDescription,1);
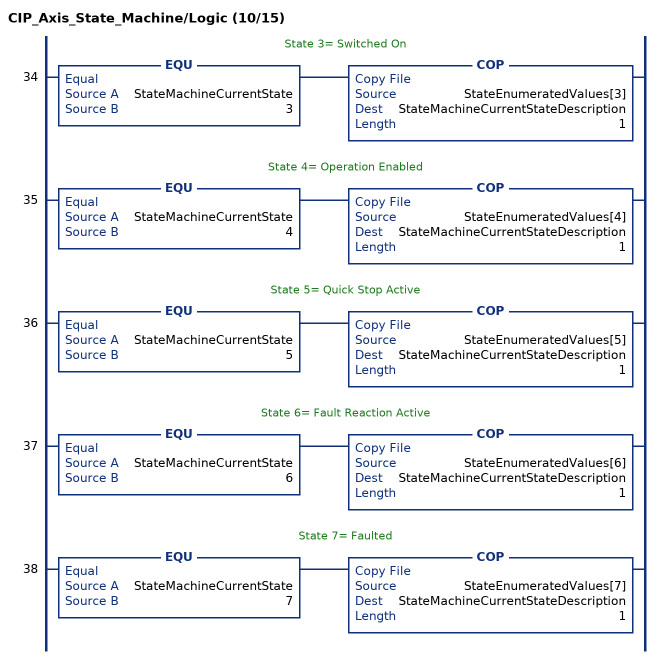
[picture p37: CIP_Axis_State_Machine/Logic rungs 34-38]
   // State 3= Switched On
   34: EQU(StateMachineCurrentState,3)COP(StateEnumeratedValues[3],StateMachineCurrentStateDescription,1);
   // State 4= Operation Enabled
   35: EQU(StateMachineCurrentState,4)COP(StateEnumeratedValues[4],StateMachineCurrentStateDescription,1);
   // State 5= Quick Stop Active
   36: EQU(StateMachineCurrentState,5)COP(StateEnumeratedValues[5],StateMachineCurrentStateDescription,1);
   // State 6= Fault Reaction Active
   37: EQU(StateMachineCurrentState,6)COP(StateEnumeratedValues[6],StateMachineCurrentStateDescription,1);
   // State 7= Faulted
   38: EQU(StateMachineCurrentState,7)COP(StateEnumeratedValues[7],StateMachineCurrentStateDescription,1);
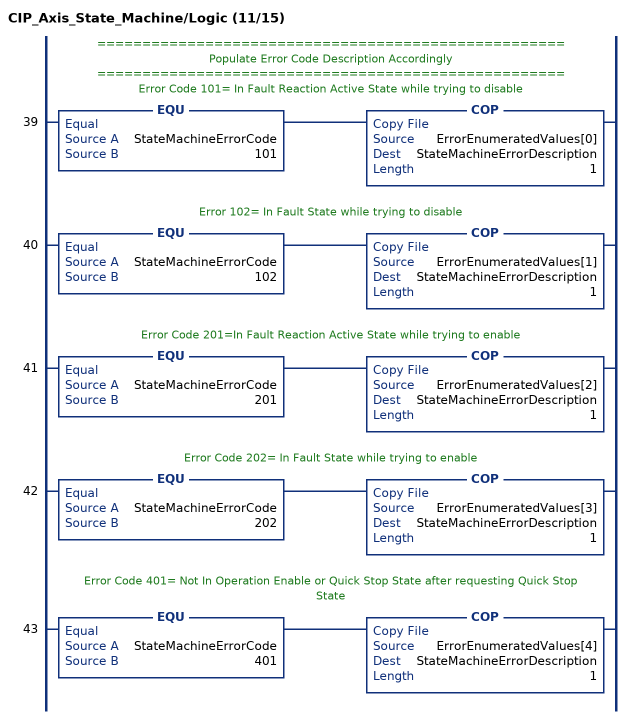
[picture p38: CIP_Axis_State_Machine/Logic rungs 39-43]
   // ====================================================
   // Populate Error Code Description Accordingly
   // ====================================================
   // Error Code 101= In Fault Reaction Active State while trying to disable
   39: EQU(StateMachineErrorCode,101)COP(ErrorEnumeratedValues[0],StateMachineErrorDescription,1);
   // Error 102= In Fault State while trying to disable
   40: EQU(StateMachineErrorCode,102)COP(ErrorEnumeratedValues[1],StateMachineErrorDescription,1);
   // Error Code 201=In Fault Reaction Active State while trying to enable
   41: EQU(StateMachineErrorCode,201)COP(ErrorEnumeratedValues[2],StateMachineErrorDescription,1);
   // Error Code 202= In Fault State while trying to enable
   42: EQU(StateMachineErrorCode,202)COP(ErrorEnumeratedValues[3],StateMachineErrorDescription,1);
   // Error Code 401= Not In Operation Enable or Quick Stop State after requesting Quick Stop State
   43: EQU(StateMachineErrorCode,401)COP(ErrorEnumeratedValues[4],StateMachineErrorDescription,1);
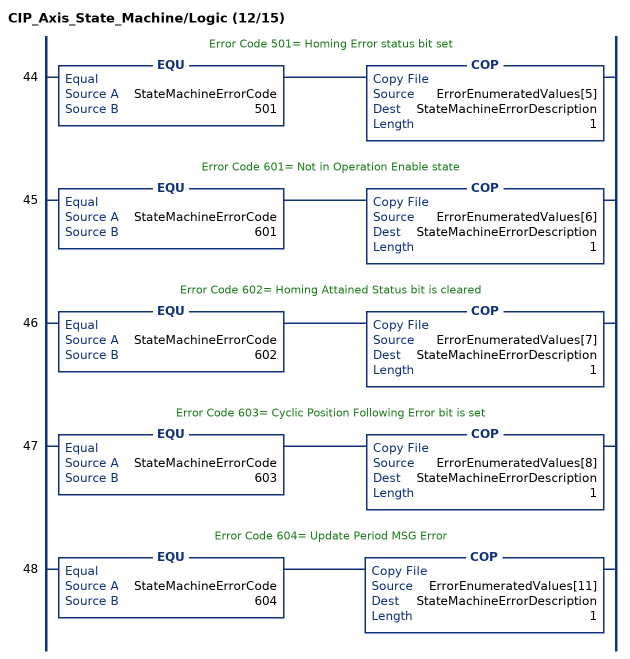
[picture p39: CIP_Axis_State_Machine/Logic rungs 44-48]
   // Error Code 501= Homing Error status bit set
   44: EQU(StateMachineErrorCode,501)COP(ErrorEnumeratedValues[5],StateMachineErrorDescription,1);
   // Error Code 601= Not in Operation Enable state
   45: EQU(StateMachineErrorCode,601)COP(ErrorEnumeratedValues[6],StateMachineErrorDescription,1);
   // Error Code 602= Homing Attained Status bit is cleared
   46: EQU(StateMachineErrorCode,602)COP(ErrorEnumeratedValues[7],StateMachineErrorDescription,1);
   // Error Code 603= Cyclic Position Following Error bit is set
   47: EQU(StateMachineErrorCode,603)COP(ErrorEnumeratedValues[8],StateMachineErrorDescription,1);
   // Error Code 604= Update Period MSG Error
   48: EQU(StateMachineErrorCode,604)COP(ErrorEnumeratedValues[11],StateMachineErrorDescription,1);
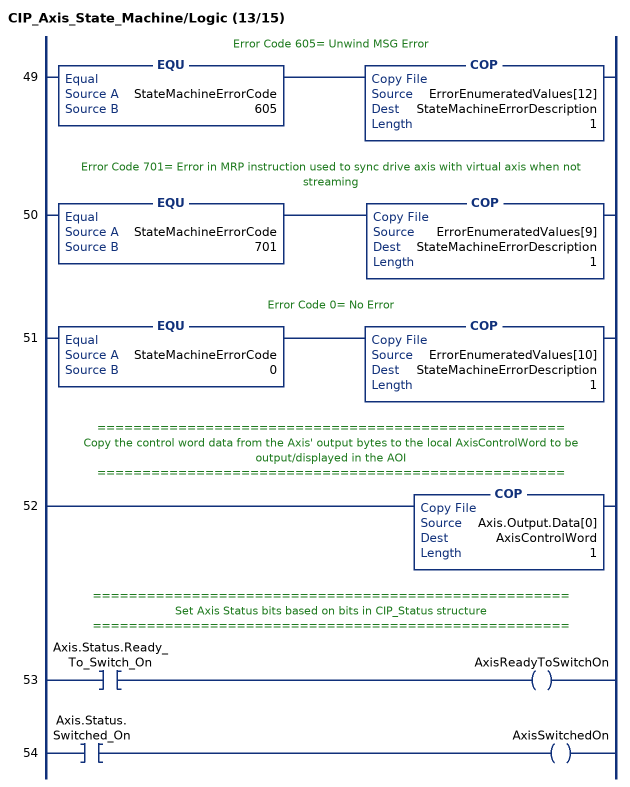
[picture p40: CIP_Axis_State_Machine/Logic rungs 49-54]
   // Error Code 605= Unwind MSG Error
   49: EQU(StateMachineErrorCode,605)COP(ErrorEnumeratedValues[12],StateMachineErrorDescription,1);
   // Error Code 701= Error in MRP instruction used to sync drive axis with virtual axis when not streaming
   50: EQU(StateMachineErrorCode,701)COP(ErrorEnumeratedValues[9],StateMachineErrorDescription,1);
   // Error Code 0= No Error
   51: EQU(StateMachineErrorCode,0)COP(ErrorEnumeratedValues[10],StateMachineErrorDescription,1);
   // ====================================================
   // Copy the control word data from the Axis' output bytes to the local AxisControlWord to be output/displayed in the AOI
   // ====================================================
   52: COP(Axis.Output.Data[0],AxisControlWord,1);
   // =====================================================
   // Set Axis Status bits based on bits in CIP_Status structure
   // =====================================================
   53: XIC(Axis.Status.Ready_To_Switch_On)OTE(AxisReadyToSwitchOn);
   54: XIC(Axis.Status.Switched_On)OTE(AxisSwitchedOn);
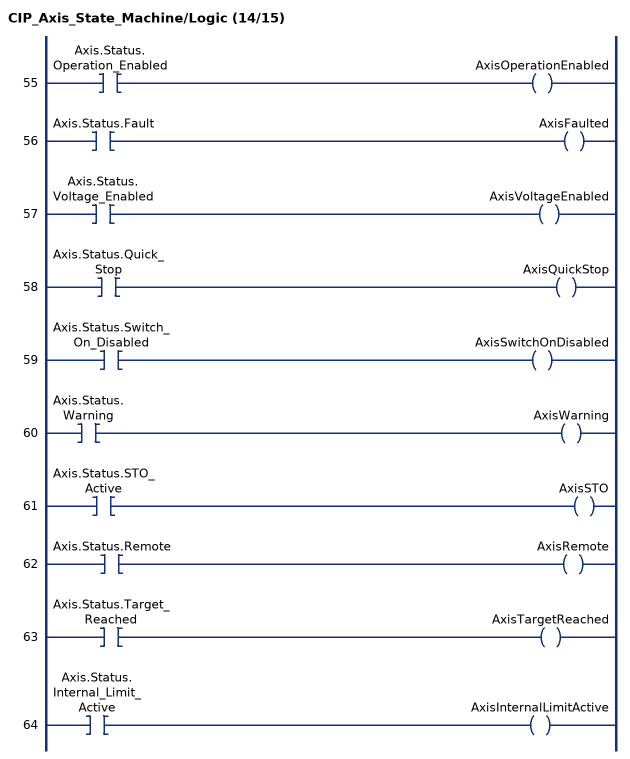
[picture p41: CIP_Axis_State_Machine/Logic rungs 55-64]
   55: XIC(Axis.Status.Operation_Enabled)OTE(AxisOperationEnabled);
   56: XIC(Axis.Status.Fault)OTE(AxisFaulted);
   57: XIC(Axis.Status.Voltage_Enabled)OTE(AxisVoltageEnabled);
   58: XIC(Axis.Status.Quick_Stop)OTE(AxisQuickStop);
   59: XIC(Axis.Status.Switch_On_Disabled)OTE(AxisSwitchOnDisabled);
   60: XIC(Axis.Status.Warning)OTE(AxisWarning);
   61: XIC(Axis.Status.STO_Active)OTE(AxisSTO);
   62: XIC(Axis.Status.Remote)OTE(AxisRemote);
   63: XIC(Axis.Status.Target_Reached)OTE(AxisTargetReached);
   64: XIC(Axis.Status.Internal_Limit_Active)OTE(AxisInternalLimitActive);
